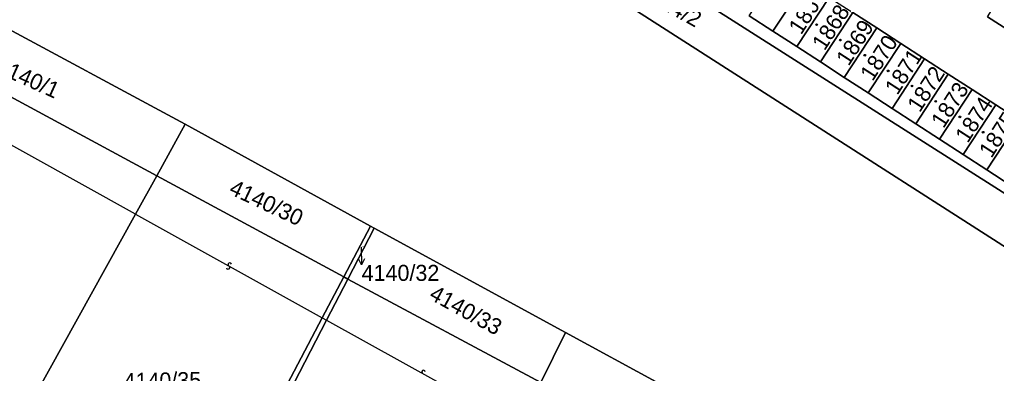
# Model space of a CAD drawing. Extents: x -598233 to -596890, y -1157848 to -1156431.
# Drawn here: x -597241.1 to -597137.7, y -1157685.3 to -1157647.8 of the extents above; entities that cross this region are included whole.
import ezdxf

# ---------------------------------------------------------------- set-up
doc = ezdxf.new("R2010")
doc.units = 0
for name, color, linetype in [('Level 1', 7, 'Continuous'), ('Level 13', 7, 'Continuous'), ('Level 3', 7, 'Continuous'), ('Level 4', 7, 'Continuous'), ('Level 5', 7, 'Continuous'), ('Level 57', 7, 'Continuous'), ('Level 60', 7, 'Continuous'), ('Vrstva 54', 7, 'Continuous'), ('Vrstva 60', 7, 'Continuous')]:
    doc.layers.add(name, color=color, linetype=linetype)

msp = doc.modelspace()

# ---------------------------------------------------------------- linework, layer by layer
at = {"layer": 'Level 1'}
for points in [[(-597409.97, -1157511.62), (-597401.88, -1157508.83), (-597373.87, -1157526.16), (-597366.75, -1157525.36), (-597335.98, -1157542.67), (-597325.9, -1157551.23), (-597302.56, -1157566.5), (-597285.2, -1157579.74), (-597270.24, -1157592.06), (-597269.3, -1157592.83), (-597259.47, -1157596.07), (-597250.85, -1157598.17), (-597245.81, -1157601.01), (-597239.94, -1157604.31), (-597223.03, -1157616.87), (-597206.27, -1157628.35), (-597179.87, -1157644.26), (-597115.94, -1157685.24), (-597093.49, -1157698.66), (-597086.96, -1157702.56), (-597050.66, -1157721.6)], [(-597144.73, -1157635.19), (-597124.59, -1157647.92), (-597112.62, -1157653.99), (-597115.75, -1157660.25), (-597114.28, -1157671.45), (-597118.54, -1157677.88), (-597228.54, -1157607.83), (-597232.29, -1157605.23), (-597228.65, -1157599.56)], [(-597245.81, -1157601.01), (-597239.94, -1157604.31), (-597223.03, -1157616.87), (-597206.27, -1157628.35), (-597179.87, -1157644.26), (-597115.94, -1157685.24)], [(-597161.39, -1157649.02), (-597157.95, -1157643.8)], [(-597155.44, -1157645.42), (-597158.87, -1157650.65)], [(-597244.22, -1157647.79), (-597223.6, -1157658.88)], [(-597161.39, -1157649.02), (-597163.92, -1157647.38)], [(-597156.36, -1157652.28), (-597152.92, -1157647.05)], [(-597152.92, -1157647.05), (-597150.4, -1157648.68)], [(-597138.66, -1157647.49), (-597136.15, -1157649.12)], [(-597158.87, -1157650.65), (-597161.39, -1157649.02)], [(-597150.4, -1157648.68), (-597153.84, -1157653.92)], [(-597150.4, -1157648.68), (-597147.86, -1157650.32)], [(-597156.36, -1157652.28), (-597158.87, -1157650.65)], [(-597151.3, -1157655.57), (-597147.86, -1157650.32)], [(-597147.86, -1157650.32), (-597145.33, -1157651.96)], [(-597148.78, -1157657.2), (-597145.33, -1157651.96)], [(-597145.33, -1157651.96), (-597142.84, -1157653.57)], [(-597153.84, -1157653.92), (-597156.36, -1157652.28)], [(-597151.3, -1157655.57), (-597153.84, -1157653.92)], [(-597142.84, -1157653.57), (-597146.27, -1157658.83)], [(-597142.84, -1157653.57), (-597140.31, -1157655.21)], [(-597226.62, -1157664.34), (-597244.78, -1157654.52), (-597263.89, -1157692.11)], [(-597143.75, -1157660.46), (-597140.31, -1157655.21)], [(-597140.31, -1157655.21), (-597137.8, -1157656.83)], [(-597148.78, -1157657.2), (-597151.3, -1157655.57)], [(-597146.27, -1157658.83), (-597148.78, -1157657.2)], [(-597137.8, -1157656.83), (-597141.25, -1157662.09)], [(-597137.8, -1157656.83), (-597135.28, -1157658.46)], [(-597226.62, -1157664.34), (-597223.6, -1157658.88)], [(-597223.6, -1157658.88), (-597204.01, -1157669.69)], [(-597143.75, -1157660.46), (-597146.27, -1157658.83)], [(-597138.75, -1157663.71), (-597135.28, -1157658.46)], [(-597141.25, -1157662.09), (-597143.75, -1157660.46)], [(-597138.75, -1157663.71), (-597141.25, -1157662.09)], [(-597228.87, -1157668.41), (-597226.62, -1157664.34)], [(-597226.62, -1157664.34), (-597206.82, -1157675.05)], [(-597136.2, -1157665.36), (-597138.75, -1157663.71)], [(-597228.87, -1157668.41), (-597245.7, -1157698.76), (-597224.61, -1157708.91)], [(-597204.01, -1157669.69), (-597206.82, -1157675.05)], [(-597204.01, -1157669.69), (-597203.62, -1157669.9)], [(-597206.39, -1157675.28), (-597203.62, -1157669.9)], [(-597203.62, -1157669.9), (-597183.34, -1157680.94)], [(-597206.82, -1157675.05), (-597209.1, -1157679.38)], [(-597208.64, -1157679.64), (-597206.39, -1157675.28)], [(-597206.39, -1157675.28), (-597206.82, -1157675.05)], [(-597185.96, -1157686.23), (-597206.39, -1157675.28)], [(-597209.1, -1157679.38), (-597224.61, -1157708.91)], [(-597223.46, -1157708.39), (-597208.64, -1157679.64)], [(-597185.96, -1157686.23), (-597183.34, -1157680.94)], [(-597163.36, -1157691.81), (-597183.34, -1157680.94)]]:
    msp.add_lwpolyline(points, dxfattribs=at)
at = {"layer": 'Level 13'}
for centre, start, end in [((-597218.89, -1157673.74), 8.3477, 240.4457), ((-597219.07, -1157674.06), 188.1332, 60.7232), ((-597198.38, -1157685.13), 8.3397, 240.4377)]:
    msp.add_arc(centre, 0.184, start, end, dxfattribs=at)
at = {"layer": 'Level 3'}
for points in [[(-597228.87, -1157668.41), (-597245.84, -1157658.99), (-597262.93, -1157692.59)], [(-597228.87, -1157668.41), (-597209.1, -1157679.38)], [(-597209.1, -1157679.38), (-597208.64, -1157679.64)], [(-597208.64, -1157679.64), (-597188.3, -1157690.93)]]:
    msp.add_lwpolyline(points, dxfattribs=at)
at = {"layer": 'Level 5'}
for centre, radius in [((-597156.76, -1157648.33), 0.09), ((-597156.76, -1157648.33), 0.0521), ((-597154.25, -1157649.97), 0.09), ((-597154.25, -1157649.97), 0.0521), ((-597151.67, -1157651.57), 0.09), ((-597151.67, -1157651.57), 0.0521), ((-597149.19, -1157653.23), 0.09), ((-597149.19, -1157653.23), 0.0521), ((-597146.67, -1157654.83), 0.09), ((-597146.67, -1157654.83), 0.0521), ((-597144.16, -1157656.46), 0.09), ((-597144.16, -1157656.46), 0.0521), ((-597141.6, -1157658.1), 0.09), ((-597141.6, -1157658.1), 0.0521), ((-597139.14, -1157659.73), 0.09), ((-597139.14, -1157659.73), 0.0521)]:
    msp.add_circle(centre, radius, dxfattribs=at)
at = {"layer": 'Level 57'}
msp.add_line((-597204.99, -1157671.89), (-597204.93, -1157673.78), dxfattribs=at)
msp.add_lwpolyline([(-597204.64, -1157673.14), (-597204.93, -1157673.78), (-597205.27, -1157673.16)], dxfattribs=at)
at = {"layer": 'Level 60'}
for points in [[(-597302.56, -1157566.5), (-597285.2, -1157579.74), (-597270.24, -1157592.06), (-597269.3, -1157592.83), (-597259.47, -1157596.07), (-597250.85, -1157598.17), (-597245.81, -1157601.01), (-597239.94, -1157604.31), (-597223.03, -1157616.87), (-597206.27, -1157628.35), (-597179.87, -1157644.26), (-597115.94, -1157685.24)], [(-597105.48, -1157726.35), (-597142.21, -1157703.35), (-597142.63, -1157703.09), (-597163.36, -1157691.81), (-597183.34, -1157680.94), (-597203.62, -1157669.9), (-597204.01, -1157669.69), (-597223.6, -1157658.88), (-597244.22, -1157647.79), (-597253.7, -1157642.01), (-597262.75, -1157636.58), (-597274.42, -1157629.37), (-597274.03, -1157628.64), (-597275.33, -1157627.77), (-597275.92, -1157628.88), (-597286.84, -1157621.88), (-597287.53, -1157622.17), (-597287.76, -1157622.64), (-597288.14, -1157622.45), (-597304.52, -1157615.14), (-597305.39, -1157615), (-597306.09, -1157615.82), (-597336.02, -1157596.93), (-597343.31, -1157592.43)], [(-597115.94, -1157685.24), (-597179.87, -1157644.26), (-597206.27, -1157628.35), (-597223.03, -1157616.87), (-597239.94, -1157604.31), (-597245.81, -1157601.01), (-597245.52, -1157600.94), (-597244.68, -1157600.76), (-597243.36, -1157600.43), (-597234.25, -1157598.31), (-597228.65, -1157599.56), (-597232.29, -1157605.23), (-597228.54, -1157607.83), (-597118.54, -1157677.88)], [(-597118.54, -1157677.88), (-597228.54, -1157607.83)], [(-597163.92, -1157647.38), (-597161.39, -1157649.02), (-597158.87, -1157650.65), (-597156.36, -1157652.28), (-597153.84, -1157653.92), (-597151.3, -1157655.57), (-597148.78, -1157657.2), (-597146.27, -1157658.83), (-597143.75, -1157660.46), (-597141.25, -1157662.09), (-597138.75, -1157663.71), (-597136.2, -1157665.36)], [(-597135.28, -1157658.46), (-597137.8, -1157656.83), (-597140.31, -1157655.21), (-597142.84, -1157653.57), (-597145.33, -1157651.96), (-597147.86, -1157650.32), (-597150.4, -1157648.68), (-597152.92, -1157647.05)], [(-597138.66, -1157647.49), (-597136.15, -1157649.12)]]:
    msp.add_lwpolyline(points, dxfattribs=at)
for points in [[(-597161.39, -1157649.02), (-597163.92, -1157647.38), (-597160.48, -1157642.16), (-597157.95, -1157643.8)], [(-597135.42, -1157642.27), (-597132.91, -1157643.9), (-597136.15, -1157649.12), (-597138.66, -1157647.49)], [(-597158.87, -1157650.65), (-597161.39, -1157649.02), (-597157.95, -1157643.8), (-597155.44, -1157645.42)], [(-597156.36, -1157652.28), (-597158.87, -1157650.65), (-597155.44, -1157645.42), (-597152.92, -1157647.05)], [(-597244.22, -1157647.79), (-597223.6, -1157658.88), (-597226.62, -1157664.34), (-597244.78, -1157654.52), (-597263.89, -1157692.11), (-597267.83, -1157690.13), (-597267.47, -1157689.5)], [(-597153.84, -1157653.92), (-597156.36, -1157652.28), (-597152.92, -1157647.05), (-597150.4, -1157648.68)], [(-597151.3, -1157655.57), (-597153.84, -1157653.92), (-597150.4, -1157648.68), (-597147.86, -1157650.32)], [(-597148.78, -1157657.2), (-597151.3, -1157655.57), (-597147.86, -1157650.32), (-597145.33, -1157651.96)], [(-597146.27, -1157658.83), (-597148.78, -1157657.2), (-597145.33, -1157651.96), (-597142.84, -1157653.57)], [(-597143.75, -1157660.46), (-597146.27, -1157658.83), (-597142.84, -1157653.57), (-597140.31, -1157655.21)], [(-597244.78, -1157654.52), (-597226.62, -1157664.34), (-597228.87, -1157668.41), (-597245.7, -1157698.76), (-597224.61, -1157708.91), (-597223.9, -1157709.25), (-597223.46, -1157708.39), (-597202.15, -1157718.82), (-597203.85, -1157722.25), (-597262.93, -1157692.59), (-597263.89, -1157692.11)], [(-597141.25, -1157662.09), (-597143.75, -1157660.46), (-597140.31, -1157655.21), (-597137.8, -1157656.83)], [(-597138.75, -1157663.71), (-597141.25, -1157662.09), (-597137.8, -1157656.83), (-597135.28, -1157658.46)], [(-597223.6, -1157658.88), (-597204.01, -1157669.69), (-597206.82, -1157675.05), (-597226.62, -1157664.34)], [(-597136.2, -1157665.36), (-597138.75, -1157663.71), (-597135.28, -1157658.46), (-597132.75, -1157660.1)], [(-597245.7, -1157698.76), (-597228.87, -1157668.41), (-597226.62, -1157664.34), (-597206.82, -1157675.05), (-597209.1, -1157679.38), (-597224.61, -1157708.91)], [(-597204.01, -1157669.69), (-597203.62, -1157669.9), (-597206.39, -1157675.28), (-597206.82, -1157675.05)], [(-597185.96, -1157686.23), (-597206.39, -1157675.28), (-597203.62, -1157669.9), (-597183.34, -1157680.94)], [(-597206.82, -1157675.05), (-597206.39, -1157675.28), (-597208.64, -1157679.64), (-597223.46, -1157708.39), (-597223.9, -1157709.25), (-597224.61, -1157708.91), (-597209.1, -1157679.38)], [(-597206.39, -1157675.28), (-597185.96, -1157686.23), (-597188.3, -1157690.93), (-597202.15, -1157718.82), (-597223.46, -1157708.39), (-597208.64, -1157679.64)], [(-597165.94, -1157697.01), (-597169.3, -1157695.16), (-597185.96, -1157686.23), (-597183.34, -1157680.94), (-597163.36, -1157691.81)]]:
    msp.add_lwpolyline(points, close=True, dxfattribs=at)
at = {"layer": 'Vrstva 54'}
msp.add_line((-597179.87, -1157644.26), (-597115.94, -1157685.24), dxfattribs=at)
at = {"layer": 'Vrstva 60'}
for points in [[(-597302.56, -1157566.5), (-597285.2, -1157579.74), (-597270.24, -1157592.06), (-597269.3, -1157592.83), (-597259.47, -1157596.07), (-597250.85, -1157598.17), (-597245.81, -1157601.01), (-597239.94, -1157604.31), (-597223.03, -1157616.87), (-597206.27, -1157628.35), (-597179.87, -1157644.26), (-597115.94, -1157685.24)], [(-597115.94, -1157685.24), (-597179.87, -1157644.26), (-597206.27, -1157628.35), (-597223.03, -1157616.87), (-597239.94, -1157604.31), (-597245.81, -1157601.01), (-597250.85, -1157598.17), (-597259.47, -1157596.07), (-597269.3, -1157592.83), (-597270.24, -1157592.06), (-597285.2, -1157579.74), (-597302.56, -1157566.5)]]:
    msp.add_lwpolyline(points, dxfattribs=at)

# ---------------------------------------------------------------- texts
at = {"layer": 'Level 4'}
for s, rotation, p in [('1867', 57.1069, (-597158.41, -1157649.49)), ('1868', 57.1069, (-597155.93, -1157651.18)), ('1869', 57.1069, (-597153.38, -1157652.8)), ('1870', 57.1069, (-597150.84, -1157654.41)), ('4140/1', 335.7, (-597243.76, -1157653.33)), ('1871', 57.1069, (-597148.22, -1157655.88)), ('1872', 57.1069, (-597145.85, -1157657.72)), ('1873', 57.1069, (-597143.33, -1157659.4)), ('1874', 57.1069, (-597140.77, -1157660.96)), ('1875', 57.1069, (-597138.26, -1157662.56)), ('4140/30', 334.8, (-597219.08, -1157666.21)), ('4140/33', 331.2, (-597197.9, -1157677.34)), ('4140/35', 0.9, (-597230.12, -1157686.95))]:
    msp.add_text(s, height=1.7, rotation=rotation, dxfattribs=at).set_placement(p)
msp.add_text('4140/32', height=0.1, dxfattribs=at).set_placement((-597204.99, -1157671.89))
at = {"layer": 'Level 57'}
msp.add_text('324/2', height=1.7, rotation=330.7318, dxfattribs=at).set_placement((-597174.54, -1157645.89))
msp.add_text('4140/32', height=1.7, dxfattribs=at).set_placement((-597204.93, -1157675.48))

doc.saveas('drawing.dxf')
